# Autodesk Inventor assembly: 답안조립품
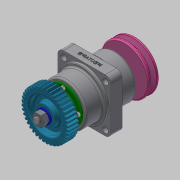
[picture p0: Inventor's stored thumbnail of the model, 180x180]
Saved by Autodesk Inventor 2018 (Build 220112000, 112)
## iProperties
Created: 2023-10
Part Number: 답안조립품
Material: 일반
Document SubType Name: Assembly
Designer: home
Author: home
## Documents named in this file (12)
- C:\Users\home\Desktop\731006V1004\답안조립품.iam
- C:\Users\home\Desktop\731006V1004\본체.ipt
- C:\Users\home\Desktop\731006V1004\커버.ipt
- C:\Users\home\Desktop\731006V1004\오일실 20x35x8.ipt
- C:\Users\home\Desktop\731006V1004\베어링 6204.ipt
- C:\Users\home\Desktop\731006V1004\축.ipt
- C:\Users\home\Desktop\731006V1004\볼트 M4x0.7.ipt
- C:\Users\home\Desktop\731006V1004\키 5x5.ipt
- C:\Users\home\Desktop\731006V1004\V벨트풀리.ipt
- C:\Users\home\Desktop\731006V1004\스퍼기어.ipt
- C:\Users\home\Desktop\731006V1004\와셔 12x24.ipt
- C:\Users\home\Desktop\731006V1004\너트 M12x1.25.ipt
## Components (1 placed, 1 different names)
1. V벨트풀리:1
